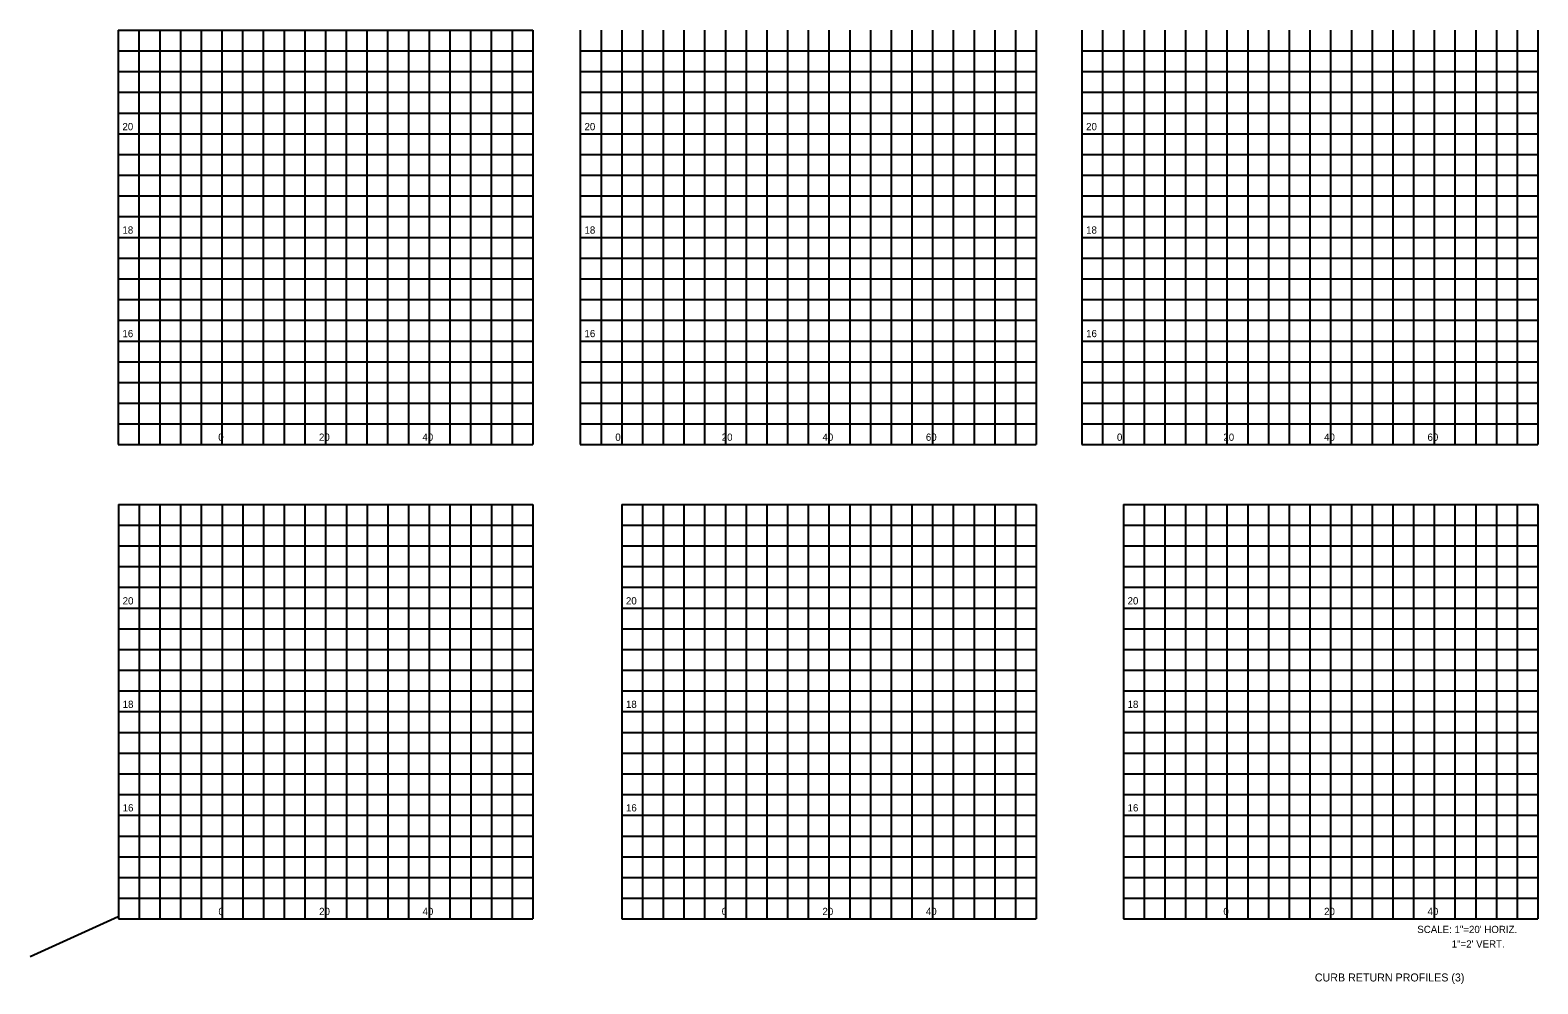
# Model space of a CAD drawing. Extents: x 127723 to 128378, y 21426 to 23736.
# Drawn here: x 127722.5 to 128013.5, y 23060.7 to 23244.7 of the extents above; entities that cross this region are included whole.
import ezdxf

# ---------------------------------------------------------------- set-up
doc = ezdxf.new("R2010")
doc.units = 0
for name, color, linetype in [('Default', 7, 'Continuous'), ('GroundCover', 7, 'Continuous'), ('Miscellaneous0', 7, 'Continuous'), ('SheetBorder_dp', 7, 'Continuous'), ('TextNotes', 7, 'Continuous')]:
    doc.layers.add(name, color=color, linetype=linetype)

msp = doc.modelspace()

# ---------------------------------------------------------------- linework, layer by layer
at = {"layer": 'Miscellaneous0'}
for p, q in [((127743.54, 23244.73), (127743.54, 23164.73)), ((127747.54, 23244.73), (127747.54, 23164.73)), ((127751.54, 23244.73), (127751.54, 23164.73)), ((127755.54, 23244.73), (127755.54, 23164.73)), ((127763.54, 23244.73), (127763.54, 23164.73)), ((127767.54, 23244.73), (127767.54, 23164.73)), ((127771.54, 23244.73), (127771.54, 23164.73)), ((127775.54, 23244.73), (127775.54, 23164.73)), ((127783.54, 23244.73), (127783.54, 23164.73)), ((127787.54, 23244.73), (127787.54, 23164.73)), ((127791.54, 23244.73), (127791.54, 23164.73)), ((127795.54, 23244.73), (127795.54, 23164.73)), ((127803.54, 23244.73), (127803.54, 23164.73)), ((127807.54, 23244.73), (127807.54, 23164.73)), ((127811.54, 23244.73), (127811.54, 23164.73)), ((127815.54, 23244.73), (127815.54, 23164.73)), ((127828.72, 23244.73), (127828.72, 23164.73)), ((127832.72, 23244.73), (127832.72, 23164.73)), ((127840.72, 23244.73), (127840.72, 23164.73)), ((127844.72, 23244.73), (127844.72, 23164.73)), ((127848.72, 23244.73), (127848.72, 23164.73)), ((127852.72, 23244.73), (127852.72, 23164.73)), ((127860.72, 23244.73), (127860.72, 23164.73)), ((127864.72, 23244.73), (127864.72, 23164.73)), ((127868.72, 23244.73), (127868.72, 23164.73)), ((127872.72, 23244.73), (127872.72, 23164.73)), ((127880.72, 23244.73), (127880.72, 23164.73)), ((127884.72, 23244.73), (127884.72, 23164.73)), ((127888.72, 23244.73), (127888.72, 23164.73)), ((127892.72, 23244.73), (127892.72, 23164.73)), ((127900.72, 23244.73), (127900.72, 23164.73)), ((127904.72, 23244.73), (127904.72, 23164.73)), ((127908.72, 23244.73), (127908.72, 23164.73)), ((127912.72, 23244.73), (127912.72, 23164.73)), ((127925.54, 23244.73), (127925.54, 23164.73)), ((127929.54, 23244.73), (127929.54, 23164.73)), ((127937.54, 23244.73), (127937.54, 23164.73)), ((127941.54, 23244.73), (127941.54, 23164.73)), ((127945.54, 23244.73), (127945.54, 23164.73)), ((127949.54, 23244.73), (127949.54, 23164.73)), ((127957.54, 23244.73), (127957.54, 23164.73)), ((127961.54, 23244.73), (127961.54, 23164.73)), ((127965.54, 23244.73), (127965.54, 23164.73)), ((127969.54, 23244.73), (127969.54, 23164.73)), ((127977.54, 23244.73), (127977.54, 23164.73)), ((127981.54, 23244.73), (127981.54, 23164.73)), ((127985.54, 23244.73), (127985.54, 23164.73)), ((127989.54, 23244.73), (127989.54, 23164.73)), ((127997.54, 23244.73), (127997.54, 23164.73)), ((128001.54, 23244.73), (128001.54, 23164.73)), ((128005.54, 23244.73), (128005.54, 23164.73)), ((128009.54, 23244.73), (128009.54, 23164.73)), ((127739.54, 23240.73), (127819.54, 23240.73)), ((127828.72, 23240.73), (127916.72, 23240.73)), ((127925.54, 23240.73), (128013.54, 23240.73)), ((127739.54, 23236.73), (127819.54, 23236.73)), ((127828.72, 23236.73), (127916.72, 23236.73)), ((127925.54, 23236.73), (128013.54, 23236.73)), ((127739.54, 23232.73), (127819.54, 23232.73)), ((127828.72, 23232.73), (127916.72, 23232.73)), ((127925.54, 23232.73), (128013.54, 23232.73)), ((127739.54, 23228.73), (127819.54, 23228.73)), ((127828.72, 23228.73), (127916.72, 23228.73)), ((127925.54, 23228.73), (128013.54, 23228.73)), ((127739.54, 23220.73), (127819.54, 23220.73)), ((127828.72, 23220.73), (127916.72, 23220.73)), ((127925.54, 23220.73), (128013.54, 23220.73)), ((127739.54, 23216.73), (127819.54, 23216.73)), ((127828.72, 23216.73), (127916.72, 23216.73)), ((127925.54, 23216.73), (128013.54, 23216.73)), ((127739.54, 23212.73), (127819.54, 23212.73)), ((127828.72, 23212.73), (127916.72, 23212.73)), ((127925.54, 23212.73), (128013.54, 23212.73)), ((127739.54, 23208.73), (127819.54, 23208.73)), ((127828.72, 23208.73), (127916.72, 23208.73)), ((127925.54, 23208.73), (128013.54, 23208.73)), ((127739.54, 23200.73), (127819.54, 23200.73)), ((127828.72, 23200.73), (127916.72, 23200.73)), ((127925.54, 23200.73), (128013.54, 23200.73)), ((127739.54, 23196.73), (127819.54, 23196.73)), ((127828.72, 23196.73), (127916.72, 23196.73)), ((127925.54, 23196.73), (128013.54, 23196.73)), ((127739.54, 23192.73), (127819.54, 23192.73)), ((127828.72, 23192.73), (127916.72, 23192.73)), ((127925.54, 23192.73), (128013.54, 23192.73)), ((127739.54, 23188.73), (127819.54, 23188.73)), ((127828.72, 23188.73), (127916.72, 23188.73)), ((127925.54, 23188.73), (128013.54, 23188.73)), ((127739.54, 23180.73), (127819.54, 23180.73)), ((127828.72, 23180.73), (127916.72, 23180.73)), ((127925.54, 23180.73), (128013.54, 23180.73)), ((127739.54, 23176.73), (127819.54, 23176.73)), ((127828.72, 23176.73), (127916.72, 23176.73)), ((127925.54, 23176.73), (128013.54, 23176.73)), ((127739.54, 23172.73), (127819.54, 23172.73)), ((127828.72, 23172.73), (127916.72, 23172.73)), ((127925.54, 23172.73), (128013.54, 23172.73)), ((127739.54, 23168.73), (127819.54, 23168.73)), ((127828.72, 23168.73), (127916.72, 23168.73)), ((127925.54, 23168.73), (128013.54, 23168.73)), ((127743.57, 23153.19), (127743.57, 23073.19)), ((127747.57, 23153.19), (127747.57, 23073.19)), ((127751.57, 23153.19), (127751.57, 23073.19)), ((127755.57, 23153.19), (127755.57, 23073.19)), ((127763.57, 23153.19), (127763.57, 23073.19)), ((127767.57, 23153.19), (127767.57, 23073.19)), ((127771.57, 23153.19), (127771.57, 23073.19)), ((127775.57, 23153.19), (127775.57, 23073.19)), ((127783.57, 23153.19), (127783.57, 23073.19)), ((127787.57, 23153.19), (127787.57, 23073.19)), ((127791.57, 23153.19), (127791.57, 23073.19)), ((127795.57, 23153.19), (127795.57, 23073.19)), ((127803.57, 23153.19), (127803.57, 23073.19)), ((127807.57, 23153.19), (127807.57, 23073.19)), ((127811.57, 23153.19), (127811.57, 23073.19)), ((127815.57, 23153.19), (127815.57, 23073.19)), ((127840.72, 23153.19), (127840.72, 23073.19)), ((127844.72, 23153.19), (127844.72, 23073.19)), ((127848.72, 23153.19), (127848.72, 23073.19)), ((127852.72, 23153.19), (127852.72, 23073.19)), ((127860.72, 23153.19), (127860.72, 23073.19)), ((127864.72, 23153.19), (127864.72, 23073.19)), ((127868.72, 23153.19), (127868.72, 23073.19)), ((127872.72, 23153.19), (127872.72, 23073.19)), ((127880.72, 23153.19), (127880.72, 23073.19)), ((127884.72, 23153.19), (127884.72, 23073.19)), ((127888.72, 23153.19), (127888.72, 23073.19)), ((127892.72, 23153.19), (127892.72, 23073.19)), ((127900.72, 23153.19), (127900.72, 23073.19)), ((127904.72, 23153.19), (127904.72, 23073.19)), ((127908.72, 23153.19), (127908.72, 23073.19)), ((127912.72, 23153.19), (127912.72, 23073.19)), ((127937.54, 23153.19), (127937.54, 23073.19)), ((127941.54, 23153.19), (127941.54, 23073.19)), ((127945.54, 23153.19), (127945.54, 23073.19)), ((127949.54, 23153.19), (127949.54, 23073.19)), ((127957.54, 23153.19), (127957.54, 23073.19)), ((127961.54, 23153.19), (127961.54, 23073.19)), ((127965.54, 23153.19), (127965.54, 23073.19)), ((127969.54, 23153.19), (127969.54, 23073.19)), ((127977.54, 23153.19), (127977.54, 23073.19)), ((127981.54, 23153.19), (127981.54, 23073.19)), ((127985.54, 23153.19), (127985.54, 23073.19)), ((127989.54, 23153.19), (127989.54, 23073.19)), ((127997.54, 23153.19), (127997.54, 23073.19)), ((128001.54, 23153.19), (128001.54, 23073.19)), ((128005.54, 23153.19), (128005.54, 23073.19)), ((128009.54, 23153.19), (128009.54, 23073.19)), ((127739.57, 23149.19), (127819.57, 23149.19)), ((127836.72, 23149.19), (127916.72, 23149.19)), ((127933.54, 23149.19), (128013.54, 23149.19)), ((127739.57, 23145.19), (127819.57, 23145.19)), ((127836.72, 23145.19), (127916.72, 23145.19)), ((127933.54, 23145.19), (128013.54, 23145.19)), ((127739.57, 23141.19), (127819.57, 23141.19)), ((127836.72, 23141.19), (127916.72, 23141.19)), ((127933.54, 23141.19), (128013.54, 23141.19)), ((127739.57, 23137.19), (127819.57, 23137.19)), ((127836.72, 23137.19), (127916.72, 23137.19)), ((127933.54, 23137.19), (128013.54, 23137.19)), ((127739.57, 23129.19), (127819.57, 23129.19)), ((127836.72, 23129.19), (127916.72, 23129.19)), ((127933.54, 23129.19), (128013.54, 23129.19)), ((127739.57, 23125.19), (127819.57, 23125.19)), ((127836.72, 23125.19), (127916.72, 23125.19)), ((127933.54, 23125.19), (128013.54, 23125.19)), ((127739.57, 23121.19), (127819.57, 23121.19)), ((127836.72, 23121.19), (127916.72, 23121.19)), ((127933.54, 23121.19), (128013.54, 23121.19)), ((127739.57, 23117.19), (127819.57, 23117.19)), ((127836.72, 23117.19), (127916.72, 23117.19)), ((127933.54, 23117.19), (128013.54, 23117.19)), ((127739.57, 23109.19), (127819.57, 23109.19)), ((127836.72, 23109.19), (127916.72, 23109.19)), ((127933.54, 23109.19), (128013.54, 23109.19)), ((127739.57, 23105.19), (127819.57, 23105.19)), ((127836.72, 23105.19), (127916.72, 23105.19)), ((127933.54, 23105.19), (128013.54, 23105.19)), ((127739.57, 23101.19), (127819.57, 23101.19)), ((127836.72, 23101.19), (127916.72, 23101.19)), ((127933.54, 23101.19), (128013.54, 23101.19)), ((127739.57, 23097.19), (127819.57, 23097.19)), ((127836.72, 23097.19), (127916.72, 23097.19)), ((127933.54, 23097.19), (128013.54, 23097.19)), ((127739.57, 23089.19), (127819.57, 23089.19)), ((127836.72, 23089.19), (127916.72, 23089.19)), ((127933.54, 23089.19), (128013.54, 23089.19)), ((127739.57, 23085.19), (127819.57, 23085.19)), ((127836.72, 23085.19), (127916.72, 23085.19)), ((127933.54, 23085.19), (128013.54, 23085.19)), ((127739.57, 23081.19), (127819.57, 23081.19)), ((127836.72, 23081.19), (127916.72, 23081.19)), ((127933.54, 23081.19), (128013.54, 23081.19)), ((127739.57, 23077.19), (127819.57, 23077.19)), ((127836.72, 23077.19), (127916.72, 23077.19)), ((127933.54, 23077.19), (128013.54, 23077.19))]:
    msp.add_line(p, q, dxfattribs=at)
at = {"layer": 'SheetBorder_dp'}
for p, q in [((127739.54, 23244.73), (127819.54, 23244.73)), ((127739.54, 23244.73), (127739.54, 23164.73)), ((127759.54, 23244.73), (127759.54, 23184.73)), ((127759.54, 23244.73), (127759.54, 23164.73)), ((127779.54, 23244.73), (127779.54, 23164.73)), ((127799.54, 23244.73), (127799.54, 23164.73)), ((127819.54, 23244.73), (127819.54, 23164.73)), ((127836.72, 23244.73), (127836.72, 23164.73)), ((127856.72, 23244.73), (127856.72, 23184.73)), ((127856.72, 23244.73), (127856.72, 23164.73)), ((127876.72, 23244.73), (127876.72, 23164.73)), ((127896.72, 23244.73), (127896.72, 23164.73)), ((127916.72, 23244.73), (127916.72, 23164.73)), ((127933.54, 23244.73), (127933.54, 23164.73)), ((127953.54, 23244.73), (127953.54, 23184.73)), ((127953.54, 23244.73), (127953.54, 23164.73)), ((127973.54, 23244.73), (127973.54, 23164.73)), ((127993.54, 23244.73), (127993.54, 23164.73)), ((128013.54, 23244.73), (128013.54, 23164.73)), ((127739.54, 23224.73), (127819.54, 23224.73)), ((127828.72, 23224.73), (127916.72, 23224.73)), ((127925.54, 23224.73), (128013.54, 23224.73)), ((127739.54, 23204.73), (127819.54, 23204.73)), ((127828.72, 23204.73), (127916.72, 23204.73)), ((127925.54, 23204.73), (128013.54, 23204.73)), ((127739.54, 23184.73), (127819.54, 23184.73)), ((127739.54, 23184.73), (127819.54, 23184.73)), ((127828.72, 23184.73), (127916.72, 23184.73)), ((127836.72, 23184.73), (127916.72, 23184.73)), ((127925.54, 23184.73), (128013.54, 23184.73)), ((127933.54, 23184.73), (128013.54, 23184.73)), ((127739.54, 23164.73), (127819.54, 23164.73)), ((127828.72, 23164.73), (127916.72, 23164.73)), ((127925.54, 23164.73), (128013.54, 23164.73)), ((127739.57, 23153.19), (127819.57, 23153.19)), ((127739.57, 23153.19), (127739.57, 23073.19)), ((127759.57, 23153.19), (127759.57, 23093.19)), ((127759.57, 23153.19), (127759.57, 23073.19)), ((127779.57, 23153.19), (127779.57, 23073.19)), ((127799.57, 23153.19), (127799.57, 23073.19)), ((127819.57, 23153.19), (127819.57, 23073.19)), ((127836.72, 23153.19), (127916.72, 23153.19)), ((127836.72, 23153.19), (127836.72, 23073.19)), ((127856.72, 23153.19), (127856.72, 23093.19)), ((127856.72, 23153.19), (127856.72, 23073.19)), ((127876.72, 23153.19), (127876.72, 23073.19)), ((127896.72, 23153.19), (127896.72, 23073.19)), ((127916.72, 23153.19), (127916.72, 23073.19)), ((127933.54, 23153.19), (128013.54, 23153.19)), ((127933.54, 23153.19), (127933.54, 23073.19)), ((127953.54, 23153.19), (127953.54, 23093.19)), ((127953.54, 23153.19), (127953.54, 23073.19)), ((127973.54, 23153.19), (127973.54, 23073.19)), ((127993.54, 23153.19), (127993.54, 23073.19)), ((128013.54, 23153.19), (128013.54, 23073.19)), ((127739.57, 23133.19), (127819.57, 23133.19)), ((127836.72, 23133.19), (127916.72, 23133.19)), ((127933.54, 23133.19), (128013.54, 23133.19)), ((127739.57, 23113.19), (127819.57, 23113.19)), ((127836.72, 23113.19), (127916.72, 23113.19)), ((127933.54, 23113.19), (128013.54, 23113.19)), ((127739.57, 23093.19), (127819.57, 23093.19)), ((127739.57, 23093.19), (127819.57, 23093.19)), ((127836.72, 23093.19), (127916.72, 23093.19)), ((127836.72, 23093.19), (127916.72, 23093.19)), ((127933.54, 23093.19), (128013.54, 23093.19)), ((127933.54, 23093.19), (128013.54, 23093.19)), ((127739.57, 23073.19), (127819.57, 23073.19)), ((127836.72, 23073.19), (127916.72, 23073.19)), ((127933.54, 23073.19), (128013.54, 23073.19))]:
    msp.add_line(p, q, dxfattribs=at)
at = {"layer": 'TextNotes'}
msp.add_line((127739.54, 23073.57), (127722.54, 23065.9), dxfattribs=at)

# ---------------------------------------------------------------- texts
at = {"layer": 'Default'}
msp.add_text('CURB RETURN PROFILES (3)', height=1.5418, dxfattribs=at).set_placement((127970.5, 23061.12))
at = {"layer": 'GroundCover'}
for s, p in [('20', (127740.35, 23225.41)), ('20', (127829.53, 23225.41)), ('20', (127926.35, 23225.41)), ('18', (127740.35, 23205.45)), ('18', (127829.53, 23205.45)), ('18', (127926.35, 23205.45)), ('16', (127740.35, 23185.47)), ('16', (127829.53, 23185.47)), ('16', (127926.35, 23185.47)), ('0', (127758.84, 23165.47)), ('20', (127778.28, 23165.47)), ('40', (127798.24, 23165.47)), ('0', (127835.48, 23165.47)), ('20', (127856.02, 23165.47)), ('40', (127875.46, 23165.47)), ('60', (127895.42, 23165.47)), ('0', (127932.3, 23165.47)), ('20', (127952.84, 23165.47)), ('40', (127972.28, 23165.47)), ('60', (127992.24, 23165.47)), ('20', (127740.39, 23133.88)), ('20', (127837.53, 23133.88)), ('20', (127934.35, 23133.88)), ('18', (127740.39, 23113.91)), ('18', (127837.53, 23113.91)), ('18', (127934.35, 23113.91)), ('16', (127740.39, 23093.93)), ('16', (127837.53, 23093.93)), ('16', (127934.35, 23093.93)), ('0', (127758.88, 23073.93)), ('20', (127778.32, 23073.93)), ('40', (127798.27, 23073.93)), ('0', (127856.02, 23073.93)), ('20', (127875.46, 23073.93)), ('40', (127895.42, 23073.93)), ('0', (127952.84, 23073.93)), ('20', (127972.28, 23073.93)), ('40', (127992.24, 23073.93)), ('SCALE: 1"=20\' HORIZ.', (127990.27, 23070.46)), ('  1"=2\' VERT.', (127995.87, 23067.66))]:
    msp.add_text(s, height=1.4, dxfattribs=at).set_placement(p)

doc.saveas('drawing.dxf')
